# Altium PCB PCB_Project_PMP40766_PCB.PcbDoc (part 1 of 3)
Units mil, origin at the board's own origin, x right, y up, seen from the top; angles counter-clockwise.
Board outline 7480.31 x 3937.01 mil, 2 copper layers (Top Layer, Bottom Layer), stack 64.8 mil thick; 214 components, 118 nets, 518 pads, 70 vias.
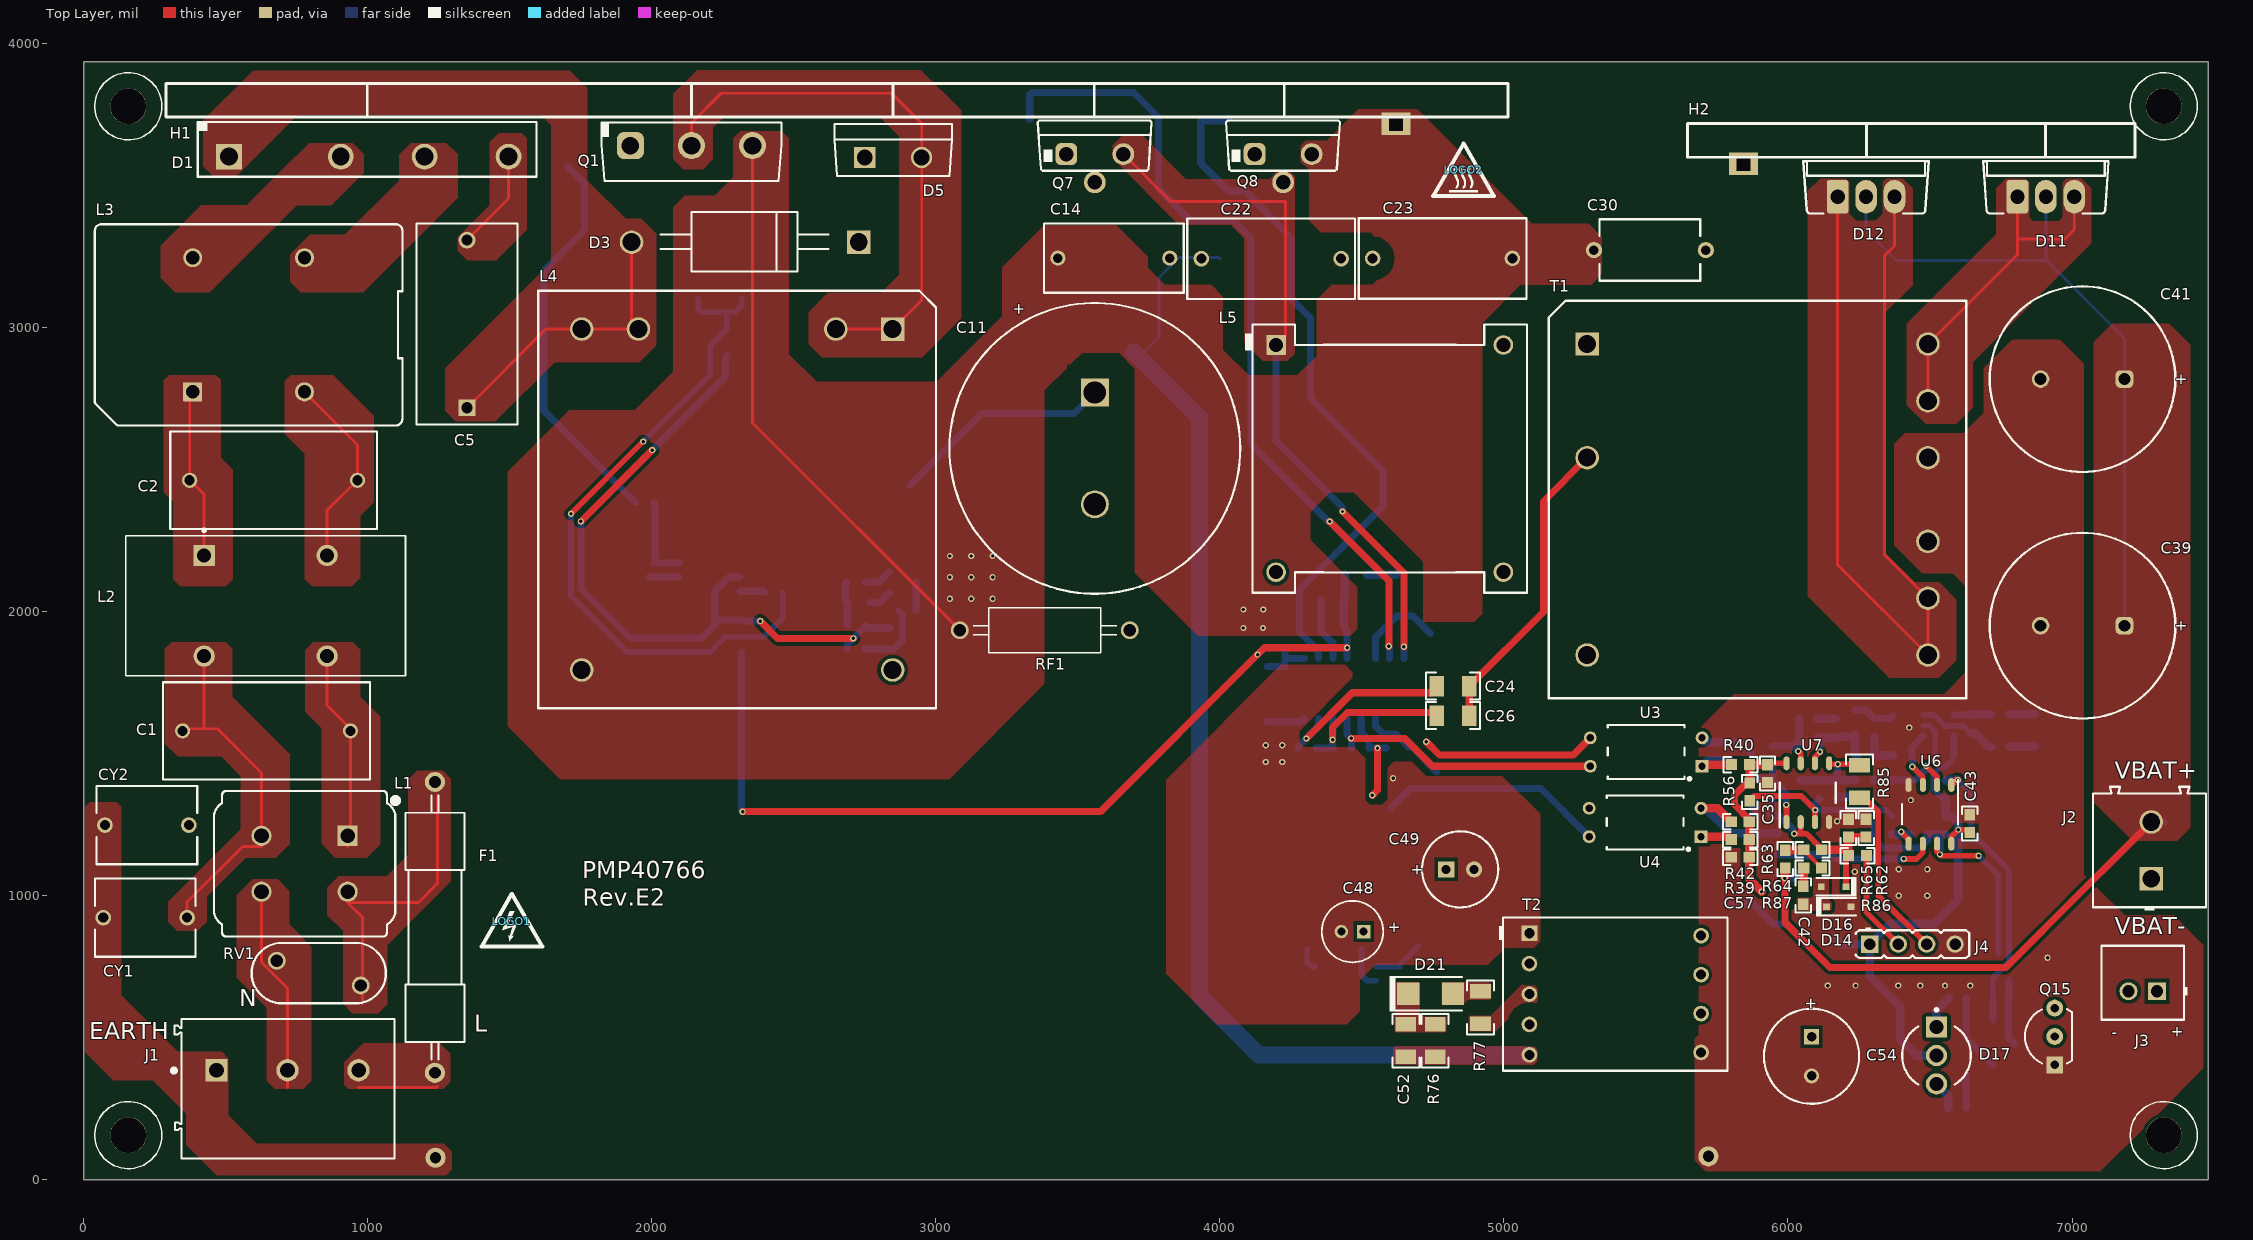
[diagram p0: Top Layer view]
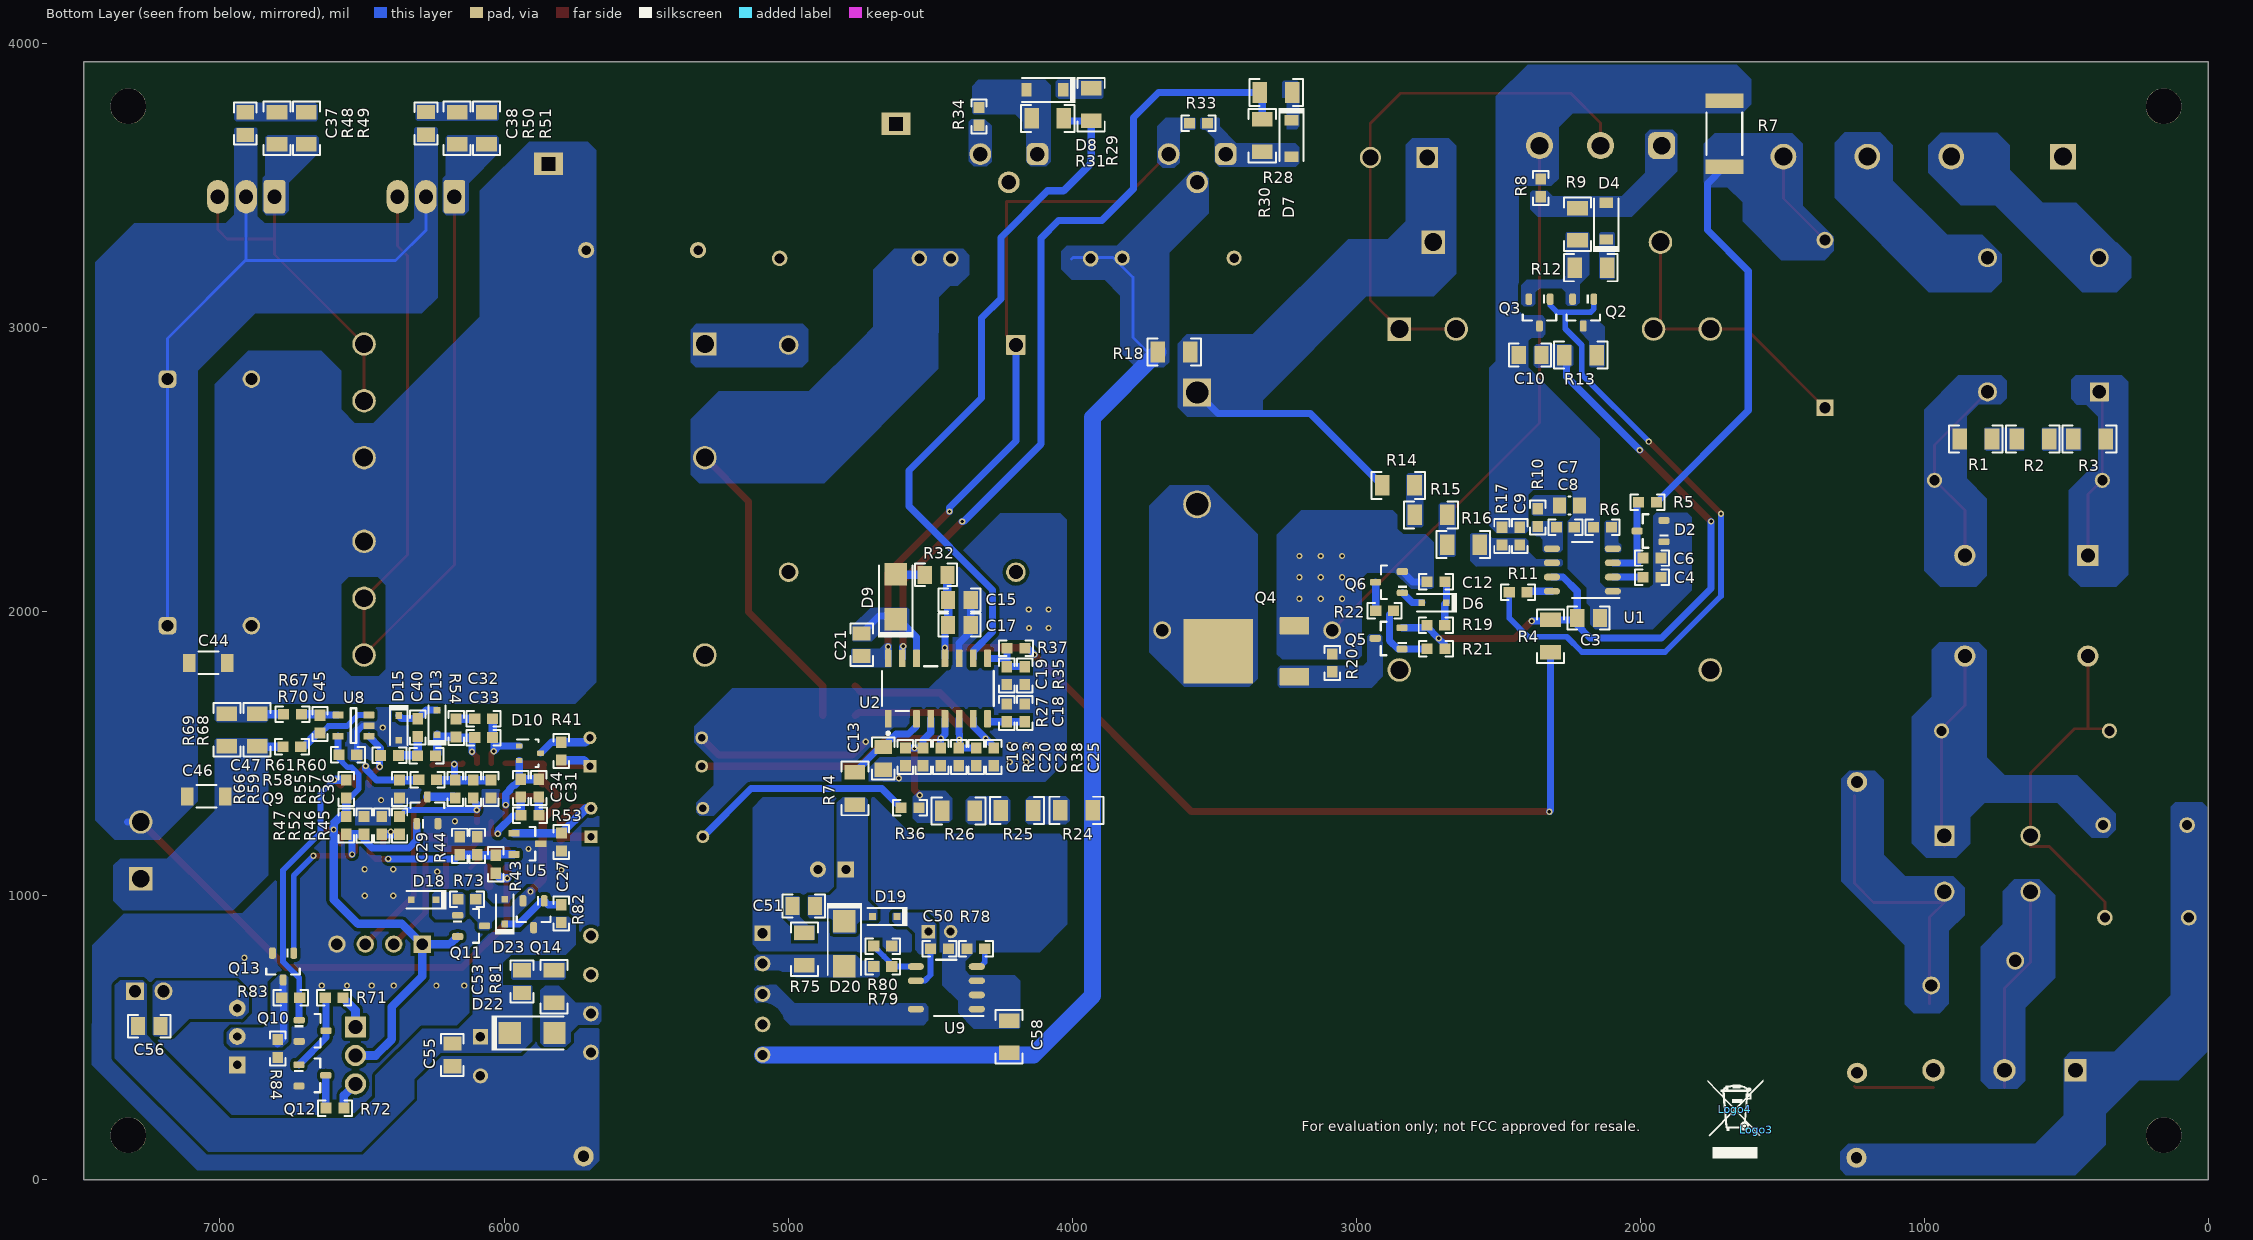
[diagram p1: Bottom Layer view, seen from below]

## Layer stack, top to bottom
Top Solder: solder mask 0.4, Solder Resist, Dk 3.5
Top Layer: signal copper 2.8
Dielectric1: core 59.2, FR-4, Dk 4.8
Bottom Layer: signal copper 2.8
Bottom Solder: solder mask 0.4, Solder Resist, Dk 3.5

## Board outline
0,0 7480.31,0 7480.31,3937.01 0,3937.01

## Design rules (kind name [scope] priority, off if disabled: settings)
AcuteAngle [All] p1: minimum=4.50000000000000E+0001 checktracksonly=FALSE
AssemblyTestPointUsage [All] p1: valid=2
Clearance Clearance_3 [InNet('EARTH') vs Not InNet('EARTH') And Not InNet('12VS')] p1: gap=129.92 ignorepadtopadclearanceinfootprint=FALSE
Clearance Clearance_1 [InNetClass('HV') vs InNetClass('MV')] p2: gap=25 ignorepadtopadclearanceinfootprint=FALSE except(0: Arc-Hole Track-Hole SMDPad-Hole THPad-Hole Via-Hole Fill-Hole Poly-Hole Region-Hole Text-Hole)
Clearance Clearance_2 [InNetClass('HV') vs Not InNetClass('HV')] p3: gap=50 ignorepadtopadclearanceinfootprint=FALSE except(0: Arc-Hole Track-Hole SMDPad-Hole THPad-Hole Via-Hole Fill-Hole Poly-Hole Region-Hole Text-Hole)
Clearance Clearance_Keepouts [((IsTrack Or IsArc) And Not InPoly) And IsFree and IsKeepOut vs ((IsTrack Or IsArc) And Not InPoly) And IsFree and IsKeepOut] p4: gap=0 ignorepadtopadclearanceinfootprint=FALSE
Clearance Clearance_BoardEdge_MountingHoles [OnCopper and InComponentClass('Mounting Holes') vs IsKeepOut] p5: gap=40 ignorepadtopadclearanceinfootprint=FALSE except(0: Arc-Hole Track-Hole SMDPad-Hole THPad-Hole Via-Hole Fill-Hole Poly-Hole Region-Hole Text-Hole)
Clearance Clearance_BoardEdge_Poly [OnCopper and InPoly vs IsKeepOut] p6: gap=25 ignorepadtopadclearanceinfootprint=FALSE except(0: Arc-Hole Track-Hole SMDPad-Hole THPad-Hole Via-Hole Fill-Hole Poly-Hole Region-Hole Text-Hole)
Clearance Clearance_BoardEdge [OnCopper and Not InComponentClass('Logo') and not InComponentClass('FiducialMark') and not InRegion(1000,500,4000,800) and Not IsKeepout vs IsKeepOut] p7: gap=75 ignorepadtopadclearanceinfootprint=FALSE except(0: Arc-Hole Track-Hole SMDPad-Hole THPad-Hole Via-Hole Fill-Hole Poly-Hole Region-Hole Text-Hole)
Clearance Clearance_Poly [InPolygon] p8: gap=12 ignorepadtopadclearanceinfootprint=FALSE
Clearance [All] p9: gap=7.87 ignorepadtopadclearanceinfootprint=FALSE except(0: Arc-Hole Track-Hole SMDPad-Hole THPad-Hole Via-Hole Fill-Hole Poly-Hole Region-Hole Text-Hole)
ComponentClearance ComponentClearance_MountingHoles_FiducialMarks [InComponentClass('Mounting Holes') vs InComponentClass('FiducialMark')] p1: gap=20 collisioncheckmode=3 verticalgap=10 showdistances=FALSE
ComponentClearance ComponentClearance_Shunt [InComponentClass('Header') vs InComponentClass('Shunt')] p2: gap=0 collisioncheckmode=3 verticalgap=0 showdistances=FALSE
ComponentClearance ComponentClearance_Logo [InComponentClass('Logo')] p3: gap=5 collisioncheckmode=3 verticalgap=10 showdistances=FALSE
ComponentClearance ComponentClearance_ScrewToNut [(HasFootprint('NY PMS 440 0025 PH')) vs (HasFootprint('Keystone_1902C'))] p4: gap=20 collisioncheckmode=3 verticalgap=100000 showdistances=FALSE
ComponentClearance ComponentClearance_MountingHoles [InComponentClass('Mounting Holes')] p5: gap=20 collisioncheckmode=3 verticalgap=10 showdistances=FALSE
ComponentClearance ComponentClearance_SmallPassives [HasFootprint('0201*') or HasFootprint('0402*') or HasFootprint('0508') or HasFootprint('0603*') or HasFootprint('0612') or HasFootprint('0805*') or HasFootprint('0815*') or HasFootprint('0830*') or HasFootprint('1206*') or HasFootprint('1210*') or HasFootprint('1808*') or HasFootprint('1812*') or HasFootprint('1825*') or HasFootprint('2010*') or HasFootprint('2220*') or HasFootprint('2225*') or HasFootprint('2512*') or HasFootprint('2728*') or HasFootprint('3518*') vs HasFootprint('0201*') or HasFootprint('0402*') or HasFootprint('0508') or HasFootprint('0603*') or HasFootprint('0612') or HasFootprint('0805*') or HasFootprint('0815*') or HasFootprint('0830*') or HasFootprint('1206*') or HasFootprint('1210*') or HasFootprint('1808*') or HasFootprint('1812*') or HasFootprint('1825*') or HasFootprint('2010*') or HasFootprint('2220*') or HasFootprint('2225*') or HasFootprint('2512*') or HasFootprint('2728*') or HasFootprint('3518*')] p6: gap=20 collisioncheckmode=3 verticalgap=20 showdistances=FALSE
ComponentClearance ComponentClearance_THtoSMT [IsThruComponent vs IsSMTComponent] p7: gap=10 collisioncheckmode=3 verticalgap=10 showdistances=FALSE
ComponentClearance ComponentClearance_THtoTH [IsThruComponent vs IsThruComponent] p8: gap=10 collisioncheckmode=3 verticalgap=10 showdistances=FALSE
ComponentClearance [All] p9: gap=10 collisioncheckmode=3 verticalgap=10 showdistances=FALSE
DiffPairsRouting [All] p1: maxlimit=100 minlimit=10 mostfreqgap=10 toplayer_minwidth=15 toplayer_maxwidth=15 toplayer_prefwidth=15 bottomlayer_minwidth=15 bottomlayer_maxwidth=15 bottomlayer_prefwidth=15 maxuncoupledlength=1000
FabricationTestPointUsage TestPointUsage [All] p1: valid=2 allowmultiple=FALSE
FabricationTestpoint Testpoint [All] p1: side=3 testpointundercomponent=TRUE minsize=40 maxsize=100 preferedsize=60 minholesize=0 maxholesize=40 preferedholesize=32 testpointgrid=1 allowsidetop=TRUE allowsidebottom=TRUE usegrid=TRUE gridtolerance=0.01
FanoutControl Fanout_LCC [IsLCC] p1: bgadir=Out bgaviamode=Centered fanoutstyle=Auto fanoutdirection=Alternating viagrid=1 // Fanout_LCC (Default Rule)
FanoutControl Fanout_BGA [IsBGA] p2: bgadir=Out bgaviamode=Centered fanoutstyle=Auto fanoutdirection=Alternating viagrid=1 // Fanout_BGA (Default Rule)
FanoutControl Fanout_Default [All] p4: bgadir=Out bgaviamode=Centered fanoutstyle=Auto fanoutdirection=Alternating viagrid=1 // Fanout_Default (Default Rule)
FanoutControl Fanout_Small [(CompPinCount < 5)] p5: bgadir=Out bgaviamode=Centered fanoutstyle=Auto fanoutdirection=OutThenIn viagrid=1 // Fanout_Small (Default Rule)
Height [All] p1: minheight=0 maxheight=3000 prefheight=500
HoleSize [All] p1: absolutevalues=TRUE maxlimit=251 minlimit=7 maxpercent=80.000 minpercent=20.000
MinimumAnnularRing MinimumAnnularRing_ThermalPadVias [IsVia and InAnyComponent] p1: minimumring=5.91
MinimumAnnularRing [All] p2: minimumring=4.9
MinimumSolderMaskSliver MinimumSolderMaskSliver_Logo [InComponentClass('Logo') vs InComponentClass('Logo')] p1: minsoldermaskwidth=0.7
MinimumSolderMaskSliver [All] p2: minsoldermaskwidth=2
PlaneConnect [All] p1: planeconnectstyle=Direct reliefexpansion=10 reliefentries=4 reliefconductorwidth=10 reliefairgap=10
PolygonConnect [All] p1: connectstyle=Direct reliefconductorwidth=10 reliefentries=4 polygonreliefangle="90 Angle" airgapwidth=10
RoutingVias ThermalPadVias [IsVia and InAnyComponent] p1: holewidth=7.87 width=19.68 viastyle="Through Hole" minholewidth=7.87 minwidth=19.68 maxholewidth=12.99 maxwidth=23.62
RoutingVias [All] p2: holewidth=16 width=34 viastyle="Through Hole" minholewidth=7.87 minwidth=20 maxholewidth=40 maxwidth=65
SilkToBoardRegionClearance [Not ((IsComment or IsDesignator) And (Hide <> 'False')) and not InRegion(1000,500,4000,800)] p1:
SilkToSilkClearance SilkToSilkClearance_Pb-FreeLogo [(HasFootprint('Pb-Free_Overlay_Medium') OR HasFootprint('Pb-Free_Overlay_Small')) vs (HasFootprint('Pb-Free_Overlay_Medium') OR HasFootprint('Pb-Free_Overlay_Small'))] p1: silktosilkclearance=0
SilkToSilkClearance [All] p2: silktosilkclearance=1
SilkToSolderMaskClearance "Silk to Solder Mask Opening" [All] p1: minsilkscreentomaskgap=1 clearancetoexposedcopper=FALSE
SolderMaskExpansion [All] p1: expansion=1.97
Width [All] p1: maxlimit=100 minlimit=6 preferedwidth=10 checkconnectedcopper=TRUE
14 further rules are at their usual default settings.

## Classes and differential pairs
net class HV: HB HO HS "N Wire" NetC1_1 NetC1_2 NetC2_1 NetC2_2 NetC5_1 NetC11_1 NetC22_2 NetC52_2 NetD1_2 NetD1_3 NetD5_2 NetD7_1 NetD7_2 NetD21_2 NetF1_1 NetR77_1 VBUS
component class PCB_Project_PMP40766_BlankSheet: C13 C14 C15 C16 C17 C18 C19 C20 C21 C22 C23 C24 C25 C26 C27 C28 C29 C30 C31 C32 C33 C34 C35 C36 C37 C38 C39 C40 C41 C42 C43 C44 C45 C46 C47 D7 D8 D9 D10 D11 D12 D13 D14 D15 D16 D17 D18 H1 H2 J2 L5 Q7 Q8 Q9 Q10 Q11 Q12 R23 R24 R25 R26 R27 R28 R29 R30 R31 R32 R33 R34 R35 R36 R37 R38 R39 R40 R41 R42 R43 R44 R45 R46 R47 R48 R49 R50 R51 R52 R53 R54 R55 R56 R57 R58 R59 R60 R61 R62 R63 R64 R65 R66 R67 R68 R69 R70 R71 R72 R73 R87 T1 U2 U3 U4 U5 U6 U7 U8
component class PCB_Project_PMP40766_CoverSheet: C1 C2 C3 C4 C5 C6 C7 C8 C9 C10 C11 C12 CY1 CY2 D1 D2 D3 D4 D5 D6 F1 J1 L1 L2 L3 L4 Q1 Q2 Q3 Q4 Q5 Q6 R1 R2 R3 R4 R5 R6 R7 R8 R9 R10 R11 R12 R13 R14 R15 R16 R17 R18 R19 R20 R21 R22 RF1 RV1 U1
component class PCB_Project_PMP40766_EVM_Hardware: C48 C49 C50 C51 C52 C53 C54 C55 C56 C57 C58 D19 D20 D21 D22 D23 J3 J4 LOGO1 LOGO2 Logo3 Logo4 Q13 Q14 Q15 R74 R75 R76 R77 R78 R79 R80 R81 R82 R83 R84 R85 R86 T2 U9
component class Header: J4

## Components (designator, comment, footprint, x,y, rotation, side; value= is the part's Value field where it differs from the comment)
C1 "R46KI347050P0K" Kemet_1800x850x1450 644,1581 r180 top value=0.47uF
C2 "R46KI347050P0K" Kemet_1800x850x1450 669,2463 r0 top value=0.47uF
C3 "GRM21BR71E475KA73L" 0805_HV 2182,1978.26 r180 bottom value=4.7uF
C4 "GRM1885C1H222JA01D" 0603 1959,2121.26 r180 bottom value=2200pF
C5 "ECW-FD2W125K" B32922_17.5mm 1350,3013.26 r90 top value=1.2uF
C6 "GRM1885C1H102FA01J" 0603 1959,2189.26 r180 bottom value=1000pF
C7 "08053C225KAT2A" 0805_150 2249,2374.26 r180 bottom value=2.2uF
C8 "C0603C105K3RACTU" 0603 2264,2297.26 r180 bottom value=1uF
C9 "GRM1885C1H271JA01D" 0603 2425,2266.26 r90 bottom value=270pF
C10 "C2012X7R1H225K125AC" 0805_HV 2388,2904.26 r0 bottom value=2.2uF
C11 "450HXG220MEFCSN25X40" HXG_2500x4000 3560,2575.26 r270 top value=220uF
C12 "GRM188R71E474KA12D" 0603 2719,2105.26 r0 bottom value=0.47uF
C13 "C2012X7R1H225K125AC" 0805_HV 4665,1484.26 r270 bottom value=2.2uF
C14 "ECW-F6223HL" ECWF_L_1250x620x1050 3627,3245 r180 top value=0.022uF
C15 "GRM21BR71E475KA73L" 0805_HV 4397,2041.26 r180 bottom value=4.7uF
C16 "GRM188R71E104KA01D" 0603 4525,1489.26 r270 bottom value=0.1uF
C17 "GRM21BR71E475KA73L" 0805_HV 4397,1953.26 r180 bottom value=4.7uF
C18 "06035A3R9CAT2A" 0603 4166.93,1644.26 r90 bottom value=3.9pF
C19 "C0603C474K4RACTU" 0603 4230,1775.26 r270 bottom value=0.47uF
C20 "GRM1885C1H101JA01D" 0603 4463,1489.26 r270 bottom value=100pF
C21 "GRM21BR71E225KA73L" 0805_HV 4741,1884 r90 bottom value=2.2uF
C22 "ECW-H8223HA" WCAP-FTX2_1500x700x1250 4181,3243 r0 top value=0.022uF
C23 "ECW-H8223HA" WCAP-FTX2_1500x700x1250 4784,3244 r0 top value=0.022uF
C24 "VJ1206A470JXGAT5Z" 1206 4821,1738.26 r180 top value=47pF
C25 "GRM188R71H822KA01D" 0603 4276,1489.26 r270 bottom value=8200pF
C26 "VJ1206A470JXGAT5Z" 1206 4821,1634.26 r180 top value=47pF
C27 "GRM188R71E224KA88D" 0603 5798,1189.26 r270 bottom value=0.22uF
C28 "GRM1885C1H101JA01D" 0603 4400,1489.26 r270 bottom value=100pF
C29 "GRM188R71E104KA01D" 0603 6156,1176.26 r90 bottom value=0.1uF
C30 "C921U222MVVDBA7317" C900_9x13 5514,3273.26 r180 top value=2200pF
C31 "C0603X103K5RACTU" 0603 5878,1379.26 r270 bottom value=0.01uF
C32 "GRM188R71E104KA01D" 0603 6072,1623.26 r0 bottom value=0.1uF
C33 "GRM188R71E102KA01D" 0603 6072,1557.26 r180 bottom value=1000pF
C34 "C0603X471K5RACTU" 0603 5941,1379.26 r90 bottom value=470pF
C35 "GRM188R71E104KA01D" 0603 5928,1430.26 r270 top value=0.1uF
C36 "GRM188R71E104KA01D" 0603 6046,1376.26 r90 bottom value=0.1uF
C37 "CL21C101JECNNWC" 0805_HV 6911,3718.37 r90 bottom value=100pF
C38 "CL21C101JECNNWC" 0805_HV 6275,3719.26 r90 bottom value=100pF
C39 "EEUFS1K681" UES_1600x2500 7037,1951.26 r180 top value=680uF
C40 "C1608X7R1E224K080AC" 0603 6304,1592.26 r90 bottom value=0.22uF
C41 "EEUFS1K681" UES_1600x2500 7037,2819.26 r180 top value=680uF
C42 "C0603X103K1RACTU" 0603 6054,1002 r270 top value=0.01uF
C43 "GRM188R71E104KA01D" 0603 6640,1254.26 r90 top value=0.1uF
C44 "GRM31CR72A105KA01L" 1206_180 7041,1820.26 r180 bottom value=1uF
C45 "GRM188R71E104KA01D" 0603 6648,1604.26 r270 bottom value=0.1uF
C46 "GRM31CR72A105KA01L" 1206_180 7048,1350.26 r180 bottom value=1uF
C47 "GRM188R71E104KA01D" 0603 6550,1496.26 r180 bottom value=0.1uF
C48 "25ML22MEFC5X5" ML_500x500 4467,874.26 r180 top value=22uF
C49 "EEU-FM1E101" FM_630x1120 4846,1093.26 r0 top value=100uF
C50 "C1608X7R1E105K080AE" 0603 4467,814.26 r180 bottom value=1uF
C51 "08051A471JAT2A" 0805_HV 4945,964.26 r180 bottom value=470pF
C52 "GRM31BR72J222KW01L" 1206 4655,490.26 r90 top value=2200pF
C53 "08051A471JAT2A" 0805_HV 5937,698.26 r90 bottom value=470pF
C54 "EKZE250ELL221MHB5D" Chemi-Con_800x1150 6083,435.26 r270 top value=220uF
C55 "GRM216R61E105KA12D" 0805_HV 6182,440.26 r270 bottom value=1uF
C56 "GRM216R61E105KA12D" 0805_HV 7249,541.26 r180 bottom value=1uF
C57 "GRM188R71E104KA01D" 0603 5832,1136.26 r180 top value=0.1uF
C58 "GRM31BR72J222KW01L" 1206 4222,504 r90 bottom value=2200pF
CY1 "DE6E3KJ222MN3A" E_900x700x900 217,923.26 r0 top value=2200pF
CY2 "DE6E3KJ222MN3A" E_900x700x900 223,1249.26 r180 top value=2200pF
D1 "GBJ2506-BP" GBJ 1004,3602.26 r0 top value=600V
D2 "BAV23CLT1G" SOT-23 1964,2284.26 r0 bottom value=250V
D3 "1N5406" DO-201AD 2329,3301.26 r180 top value=600V
D4 "1N4148W-7-F" SOD-123 2120,3375.26 r90 bottom value=100V
D5 "C3D04060A" TO-220-F2 2850,3599.26 r0 top value=600V
D6 "MM3Z5V1ST1G" SOD-323 2726,2032.26 r0 bottom value=5.1V
D7 "1N4148W-7-F" SOD-123 3228,3666.26 r270 bottom value=100V
D8 "1N4148W-7-F" SOD-123 4096,3837.26 r0 bottom value=100V
D9 "ES1JTR" SMA 4621,2053 r90 bottom value=600V
D10 "BAT54AWT-TP" SOT-323 5909,1502.26 r180 bottom value=30V
D11 "TST20L200CW C0G" TO-220AB 6908,3461.26 r0 top value=200V
D12 "TST20L200CW C0G" TO-220AB 6275,3461.26 r0 top value=200V
D13 "BAT43WS-7-F" SOD-323 6236,1610.26 r90 bottom value=30V
D14 "BAT43WS-7-F" SOD-323 6179,962 r0 top value=30V
D15 "BAT43WS-7-F" SOD-323 6371,1591.26 r270 bottom value=30V
D16 "BAT43WS-7-F" SOD-323 6161,1032 r180 top value=30V
D17 "MT6224-AHRG-A" FP-MT6224-AHRG-A_RADIAL-MFG 6523,438 r270 top
D18 "MM3Z5V6ST1G" SOD-323 6283,986.26 r0 bottom value=5.6V
D19 "1N4148WX-TP" SOD-323 4660,927.26 r0 bottom value=75V
D20 "ES1D-13-F" SMA 4802,831.26 r270 bottom value=200V
D21 "US1M-13-F" SMA 4742,655.26 r0 top value=1000V
D22 "ES1D-13-F" SMA 5901,517.26 r180 bottom value=200V
D23 "MM3Z11VST1G" SOD-323 5998,944.26 r90 bottom value=11V
F1 "0216010.MXEP" FUSE_0216 1237,889 r270 top
H1 "40mm*120mm" Heatsink1 290,3741.26 r0 top
H2 "" Heatsink2 5647,3600.26 r0 top
J1 "1714968" Phoenix_1714968 718,386 r0 top
J2 "691216510002S" Wurth_691216510002 7279,1160.26 r90 top
J3 "705430001" Molex_0705430001 7249,664.26 r180 top
J4 "22284043" Molex_0022284043 6438.44,830 r0 top
L1 "744842932" WE-CMB_NiZn_S 778,1113 r270 top value=32uH
L2 "YXBCM020013007C" FP-YXBCM020013007C_PTH_CHOKE_12MM5_25MM0-MFG 641,2021.26 r90 top
L3 "7448040707" WE-CMBNC_L 581,3010.26 r90 top value=7mH
L4 "" PQ3230_1 2301,2395.26 r270 top value=340uH
L5 "" PQ2020 4598,2539.26 r0 top value=58uH
LOGO1 "DANGER HIGH VOLTAGE" IEC_HighVoltage_Small 1508,910 r0 top
LOGO2 "CAUTION HOT SURFACE" IEC_HotSurface_Small 4858,3556.26 r0 top
Logo3 "FCC disclaimer" FCC_disclaimer 1592,177 r180 bottom
Logo4 "WEEE logo" WEEE_Minimum 1667,248 r180 bottom
Q1 "IPW60R080P7XKSA1" TO-247 2140,3641.26 r0 top value=600V
Q2 "MMBT2222ALT1G" SOT-23 2201,3053.26 r270 bottom value="40 V"
Q3 "MMBT2907ALT1G" SOT-23 2355,3053.26 r270 bottom value="60 V"
Q4 "IPD60R180P7SAUMA1" DPAK 3352,1861.26 r0 bottom value=600V
Q5 "MMBT3906LT1G" SOT-23 2886,1906.26 r0 bottom value="40 V"
Q6 "MMBT3904LT1G" SOT-23 2885,2104.26 r0 bottom value="40 V"
Q7 "IPA60R170CFD7XKSA1" TO-220FP 3560,3611.26 r0 top value=600V
Q8 "IPA60R170CFD7XKSA1" TO-220FP 4223,3611.26 r0 top value=600V
Q9 "2N7002-7-F" SOT-23 6270,1301.26 r90 bottom value=60V
Q10 "2N7002-7-F" SOT-23 6674,525 r180 bottom value=60V
Q11 "MMBT3904LT1G" SOT-23 6116,894.26 r180 bottom value="40 V"
Q12 "2N7002-7-F" SOT-23 6675,368 r180 bottom value=60V
Q13 "2N7002-7-F" SOT-23 6778,751 r270 bottom value=60V
Q14 "MMBT3904LT1G" SOT-23 5896,935.26 r270 bottom value="40 V"
Q15 "2N4401-AP" TO-92AP 6939,505 r90 top value="40 V"
R1 "RC1206FR-07330KL" 1206 819,2608.26 r0 bottom value=330k
R2 "RC1206FR-07330KL" 1206 618,2608.26 r0 bottom value=330k
R3 "RC1206FR-07330KL" 1206 419,2608.26 r0 bottom value=330k
R4 "RC1206JR-070RL" 1206 2316,1914.26 r90 bottom value=0
R5 "RC0603FR-07220RL" 0603 1975,2385.26 r180 bottom value=220
R6 "RC0603FR-0721K5L" 0603 2133,2298.26 r180 bottom value=21.5k
R7 "CSRN2512FK20L0" 2512 1704,3683.26 r90 bottom value=0.02
R8 "RC0603FR-0710KL" 0603 2350,3492.26 r270 bottom value=10.0k
R9 "RC1206FR-073R3L" 1206 2221,3364.26 r90 bottom value=3.30
R10 "RC0603FR-0711K5L" 0603 2361,2331.26 r270 bottom value=11.5k
R11 "RC0603FR-0710RL" 0603 2430,2068.26 r0 bottom value=10.0
R12 "RC1206FR-073R3L" 1206 2174,3211.26 r180 bottom value=3.30
R13 "RC1206FR-073R3L" 1206 2210,2903.26 r180 bottom value=3.30
R14 "RC1206FR-071ML" 1206 2852,2445.26 r0 bottom value=1.00Meg
R15 "RC1206FR-071ML" 1206 2737,2341.26 r0 bottom value=1.00Meg
R16 "RC1206FR-071ML" 1206 2623,2236.26 r0 bottom value=1.00Meg
R17 "RC0603FR-0739KL" 0603 2487,2266.26 r270 bottom value=39.0k
R18 "RC1206JR-070RL" 1206 3641,2914.26 r0 bottom value=0
R19 "RC0603FR-07100KL" 0603 2720,1952.26 r0 bottom value=100k
R20 "RC0603FR-0710KL" 0603 3084,1820.26 r270 bottom value=10.0k
R21 "RC0603FR-07100KL" 0603 2719,1869.26 r180 bottom value=100k
R22 "RC0603FR-07100KL" 0603 2900,2004.26 r180 bottom value=100k
R23 "RC0603FR-07121KL" 0603 4587,1489.26 r90 bottom value=121k
R24 "CRCW12064M99FKEA" 1206 3985,1301.26 r180 bottom value=4.99Meg
R25 "CRCW12064M99FKEA" 1206 4194,1300.26 r180 bottom value=4.99Meg
R26 "CRCW12064M99FKEA" 1206 4400,1299.26 r180 bottom value=4.99Meg
R27 "RC0603FR-074K53L" 0603 4230,1644.26 r270 bottom value=4.53k
R28 "RC1206FR-071RL" 1206 3282,3828.26 r180 bottom value=1.00
R29 "RC1206FR-071RL" 1206 3933,3785.26 r90 bottom value=1.00
R30 "RC1206FR-0710RL" 1206 3331,3676.26 r270 bottom value=10.0
R31 "RC1206FR-0710RL" 1206 4086,3737.26 r0 bottom value=10.0
R32 "RC0805FR-072R2L" 0805_HV 4479,2130 r0 bottom value=2.20
R33 "RC0603FR-0710KL" 0603 3555,3719.26 r180 bottom value=10.0k
R34 "RC0603FR-0710KL" 0603 4328,3744.26 r90 bottom value=10.0k
R35 "RC0603FR-0782KL" 0603 4167,1775.26 r90 bottom value=82.0k
R36 "RC0603FR-0751KL" 0603 4571,1310.26 r180 bottom value=51.0k
R37 "RC0603FR-07200KL" 0603 4198,1871.26 r0 bottom value=200k
R38 "RC0603FR-07180RL" 0603 4338,1489.26 r90 bottom value=180
R39 "RC0603FR-073KL" 0603 5832,1198.26 r0 top value=3.00k
R40 "RC0603FR-076K04L" 0603 5833,1462.26 r0 top value=6.04k
R41 "RC0603FR-073KL" 0603 5799,1509.26 r90 bottom value=3.00k
R42 "RC0603FR-0710KL" 0603 5832,1260.26 r0 top value=10.0k
R43 "RC0603FR-07301KL" 0603 6029,1111.26 r270 bottom value=301k
R44 "RC0603FR-0710KL" 0603 6094,1176.26 r270 bottom value=10.0k
R45 "RC0603FR-075K1L" 0603 6368,1248.26 r90 bottom value=5.10k
R46 "RC0603FR-077K5L" 0603 6431,1248.26 r270 bottom value=7.50k
R47 "RC0603FR-075K1L" 0603 6555,1248.26 r90 bottom value=5.10k
R48 "RC1206FR-0710RL" 1206 6799,3702.26 r90 bottom value=10.0
R49 "RC1206FR-0710RL" 1206 6696,3702.26 r90 bottom value=10.0
R50 "RC1206FR-0710RL" 1206 6165,3702.26 r90 bottom value=10.0
R51 "RC1206FR-0710RL" 1206 6062,3702.26 r90 bottom value=10.0
R52 "RC0603FR-0710KL" 0603 6493,1248.26 r270 bottom value=10.0k
R53 "RC0603FR-0768KL" 0603 5909,1284.26 r180 bottom value=68.0k
R54 "RC0603FR-072K4L" 0603 6169,1591.26 r270 bottom value=2.40k
R55 "RC0603FR-07187RL" 0603 6172,1376.26 r90 bottom value=187
R56 "RC0603FR-073KL" 0603 5866,1366.26 r270 top value=3.00k
R57 "RC0603FR-072K4L" 0603 6109,1376.26 r270 bottom value=2.40k
R58 "RC0603FR-075K1L" 0603 6269,1408.26 r180 bottom value=5.10k
R59 "RC0603FR-07499RL" 0603 6368,1376.26 r90 bottom value=499
R60 "RC0603FR-072KL" 0603 6273,1493.26 r0 bottom value=2.00k
R61 "RC0603FR-0720RL" 0603 6403,1494.26 r180 bottom value=20.0
R62 "CRCW060312K4FKEA" 0603 6275,1238.26 r270 top value=12.4k
R63 "RC0603FR-0720RL" 0603 5991,1129.26 r270 top value=20.0
R64 "RC0603FR-07100KL" 0603 6087,1162.26 r180 top value=100k
R65 "RC0603FR-075K11L" 0603 6213,1238.26 r270 top value=5.11k
R66 "RC0603FR-071KL" 0603 6556,1376.26 r90 bottom value=1.00k
R67 "RC0603FR-0710RL" 0603 6745,1639.26 r0 bottom value=10.0
R68 "CSR1206FK10L0" 1206 6869,1584.26 r270 bottom value=0.01
R69 "CSR1206FK10L0" 1206 6976,1584.26 r270 bottom value=0.01
R70 "RC0603FR-0710RL" 0603 6747,1524.26 r0 bottom value=10.0
R71 "RC0603FR-07510RL" 0603 6598,641 r180 bottom value=510
R72 "RC0603FR-07510RL" 0603 6595,253 r180 bottom value=510
R73 "RC0603FR-073K6L" 0603 6131,988.26 r0 bottom value=3.60k
R74 "RC1206JR-070RL" 1206 4765,1378.26 r270 bottom value=0
R75 "RC1206FR-0710RL" 1206 4943,812.26 r270 bottom value=10.0
R76 "RC1206FR-07200KL" 1206 4758,490.26 r270 top value=200k
R77 "RC1206FR-07200RL" 1206 4918,607.26 r90 top value=200
R78 "RC0603FR-071K8L" 0603 4339,813.26 r180 bottom value=1.80k
R79 "RC0603FR-0782KL" 0603 4667,751.26 r0 bottom value=82.0k
R80 "RC0603FR-0730KL" 0603 4667,823.26 r0 bottom value=30.0k
R81 "RC1206FR-0710RL" 1206 5824,680.26 r90 bottom value=10.0
R82 "RC0603FR-073KL" 0603 5799,937.26 r90 bottom value=3.00k
R83 "RC0603FR-071KL" 0603 6751,641 r180 bottom value=1.00k
R84 "RC0603FR-0710KL" 0603 6797,463 r90 bottom value=10.0k
R85 "RC1206FR-0710KL" 1206 6252,1402.5 r270 top value=10.0k
R86 "RC0603FR-0710KL" 0603 6245,1142 r180 top value=10.0k
R87 "RC0603FR-07150KL" 0603 6087,1098 r0 top value=150k
RF1 "EMC2-47RKI" EMC2 3384,1935.26 r180 top value=47
RV1 "S10K275E2" VAR_S10K275E2 828,728 r180 top value=275V
T1 "" PQ3230_2 5893,2395.26 r0 top value=200uH
T2 "RLTI-1168" Renco_RLTI-1186 5392,654.26 r0 top value=1800uH
U1 "UCC28180DR" D0008A_N 2204,2147.26 r0 bottom
U2 "UCC256403DDBR" DDB0014A-MFG 4473,1729.77 r90 bottom
U3 "FOD817A" DIP-4 5501,1506.26 r180 top
U4 "FOD817A" DIP-4 5497,1258.26 r180 top
U5 "TL431LIAIDBZR" DBZ0003A_N 5918,1183.26 r180 bottom
U6 "LMV393IDR" D0008A_L 6500,1287 r270 top
U7 "TL103WAIDR" D0008A_L 6070,1363.26 r90 top
U8 "INA180A2IDBVR" DBV0005A_N 6530,1599.26 r0 bottom
U9 "UCC28910DR" D0007A_N 4443,676.26 r0 bottom

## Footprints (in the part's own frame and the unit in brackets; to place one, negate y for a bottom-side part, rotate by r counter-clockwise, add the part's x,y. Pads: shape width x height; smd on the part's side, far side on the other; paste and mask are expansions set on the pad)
0603 [mm] "0603 from SM-752 data"
  rect 1x0.95 smd: 1(-0.8,0) 2(0.8,0)
  silkscreen extent -1.52,-0.69 1.52,0.69, body extent -0.87,-0.47 0.87,0.47, height 1
0805_150 [mm] "0805 / 1.5 mm height"
  rect 1.15x1.45 smd: 1(-0.9,0) 2(0.9,0)
  silkscreen extent -0.1,-0.8 0.1,0.8, body extent -1.1,-0.72 1.1,0.72, height 1.5
0805_HV [mil] "0805 with 30mil clearance between pads"
  rect 50x63 smd: 1(-40,0) 2(40,0)
  silkscreen extent -74,-40 74,40, body extent -43,-29 43,29, height 57
1206 [mm] "1206 from SM-752 data"
  rect 1.3x1.85 smd: 1(-1.45,0) 2(1.45,0)
  silkscreen extent -2.4,-1.21 2.4,1.21, body extent -1.7,-0.9 1.7,0.9, height 1.35
1206_180 [mm] "1206_180"
  rect 1.1x1.6 smd: 1(-1.7,0) 2(1.7,0)
  silkscreen extent -0.9,-1 0.9,1, body extent -1.75,-0.95 1.75,0.95, height 1.8
2512 [mm] "Chip Resistor, Body 6.3x3.2mm, IPC Medium Density"
  rect 1.3x3.4 smd: 1(-2.95,0) 2(2.95,0)
  silkscreen extent -1.9,-1.6 1.9,1.6, body extent -3.22,-1.67 3.22,1.67, height 0.71
B32922_17.5mm [mm] "Epcos film capacitors, 15mm spacing"
  rect 1.5x1.5 hole 1: 1(-7.5,0)
  round 1.5 hole 1: 2(7.5,0)
  silkscreen extent -9,-4.5 9,4.5, body extent -9,-4.5 9,4.5, height 17.5
C900_9x13 [mm] "Kemet"
  round 1.45 hole 0.85: 1(-5,0) 2(5,0)
  silkscreen extent -4.5,-2.75 4.5,2.75, body extent -4.49,-2.75 4.49,2.75, height 12.96
Chemi-Con_800x1150 [mm] "TH, 2-Leads, Dia 8mm"
  rect 1.35x1.35 hole 0.85: 1(-1.75,0)
  round 1.35 hole 0.85: 2(1.75,0)
  silkscreen extent -4.25,-4.25 4.25,4.25, body extent -4.22,-4.24 4.24,4.24, height 13.01
D0007A_N [mm] "SOIC, 7-Leads, Body 4.9x3.9mm, Pitch 1.27mm, IPC Medium Density"
  oval 1.45x0.6 smd: 1(-2.725,1.905) 2(-2.725,0.635) 3(-2.725,-0.635) 4(-2.725,-1.905) 5(2.725,-1.905) 6(2.725,-0.635) 8(2.725,1.905)
  silkscreen extent -3.32,-2.5 1.1,2.52, body extent -3.01,-2.45 3.01,2.45, height 1.75
D0008A_L [mm] "SOIC, 8-Leads, Body 4.9x3.9mm, Pitch 1.27mm, IPC High Density"
  oval 1.25x0.55 smd: 1(-2.625,1.905) 2(-2.625,0.635) 3(-2.625,-0.635) 4(-2.625,-1.905) 5(2.625,-1.905) 6(2.625,-0.635) 7(2.625,0.635) 8(2.625,1.905)
  silkscreen extent -3.1,-2.5 0.9,2.5, body extent -3,-2.45 3,2.45, height 1.63
D0008A_N [mm] "SOIC, 8-Leads, Body 4.9x3.9mm, Pitch 1.27mm, IPC Medium Density"
  oval 1.45x0.6 smd: 1(-2.725,1.905) 2(-2.725,0.635) 3(-2.725,-0.635) 4(-2.725,-1.905) 5(2.725,-1.905) 6(2.725,-0.635) 7(2.725,0.635) 8(2.725,1.905)
  silkscreen extent -3.3,-2.5 0.9,2.5, body extent -3,-2.45 3,2.45, height 1.63
DBV0005A_N [mm] "SOT23, 5-Leads, Body 2.9x1.6mm, Pitch 0.95mm, Lead Span 2.8mm, IPC Medium Density"
  rrect17% 1x0.6 smd: 1(-1.375,0.95) 2(-1.375,0) 3(-1.375,-0.95) 4(1.375,-0.95) 5(1.375,0.95)
  silkscreen extent -0.25,-1.55 0.25,1.55, body extent -1.42,-1.46 1.42,1.46, height 1.09
DBZ0003A_N [mm] "SOT23, 3-Leads, Body 2.9x1.3mm, Pitch 0.95mm, Lead Span 2.4mm, IPC Medium Density"
  rrect17% 1x0.6 smd: 1(-1.2,0.95) 2(-1.2,-0.95) 3(1.2,0)
  silkscreen extent 0.2,-1.5 0.7,1.5, body extent -1.26,-1.46 1.26,1.46, height 0.98
DDB0014A-MFG [mm]
  rrect17% 1.55x0.6 smd paste+0 mask+0: 1(-2.7,4.445) 3(-2.7,1.905) 4(-2.7,0.635) 5(-2.7,-0.635) 6(-2.7,-1.905) 7(-2.7,-3.175) 8(-2.7,-4.445) 9(2.7,-4.445) 10(2.7,-3.175) 11(2.7,-1.905) 12(2.7,-0.635) 14(2.7,1.905) 15(2.7,3.175) 16(2.7,4.445)
  silkscreen extent -4.12,-5 2,5, body extent -3.01,-4.95 3.01,4.95, height 1.75
DIP-4 [mm] "DIP, 4-Leads, Body 6.86x4.83mm, Pitch 2.54mm"
  rect 1.15x1.15 hole 0.65: 1(-5,1.27)
  round 1.15 hole 0.65: 2(-5,-1.27) 3(5,-1.27) 4(5,1.27)
  silkscreen extent -4,-2.41 3.43,2.52, body extent -4.44,-2.41 4.4,2.41, height 5.59
DO-201AD [mm] "Vishay dimensions"
  rect 2.1x2.1 hole 1.6: 1(-10.16,0)
  round 2.1 hole 1.6: 2(10.16,0)
  silkscreen extent -7.47,-2.7 7.57,2.61, body extent -10.82,-2.74 10.82,2.61, height 5.33
DPAK [mm] "D-PAK, 3-Pads, Body 6.22x6.73mm (max), TO-252AA using nominal STEP model"
  rrect6% 2.6x1.6 smd: 1(-3.4,2.28) 3(-3.4,-2.28)
  rrect2% 6.2x5.8 smd paste-3: 2(3.4,0)
  body extent -3.86,-3.29 5.84,3.29, height 2.48
E_900x700x900 [mm] "TH, 2- Leads, Body 9x7mm, Pin Spacing 7.5mm"
  round 1.4 hole 0.9: 1(-3.75,0) 2(3.75,0)
  silkscreen extent -4.5,-3.5 4.5,3.5, body extent -4.49,-3.5 4.49,3.5, height 11.96
ECWF_L_1250x620x1050 [mm] "TH, 2-Leads, Body 12.5x6.2mm, Pin Spacing 10mm"
  round 1.35 hole 0.85: 1(-5,0) 2(5,0)
  silkscreen extent -6.25,-3.1 6.25,3.1, body extent -6.25,-3.1 6.25,3.1, height 10.5
EMC2 [mm] "Welwyn"
  round 1.6 hole 1.1: 1(-7.6,0) 2(7.6,0)
  silkscreen extent -6.42,-2 6.42,2, body extent -8.02,-2 8.02,2, height 3.98
FCC_disclaimer [mil]
FM_630x1120 [mm] "PANASONIC"
  rect 1.45x1.45 hole 0.787: 1(-1.25,0)
  round 1.45 hole 0.787: 2(1.25,0)
  silkscreen extent -3.4,-3.4 3.4,3.4, body extent -3.37,-3.39 3.4,3.39, height 12.71
FP-MT6224-AHRG-A_RADIAL-MFG [mm]
  rrect5% 1.9x1.9 hole 1.25 paste-1000 mask+0: 1(-2.54,0)
  round 1.9 hole 1.25 paste-1000 mask+0: 2(0,0) 3(2.54,0)
  silkscreen extent -4.2,-3.07 2.6,3.07, body extent -3.72,-3.72 3.72,3.72, height 0.25
FP-YXBCM020013007C_PTH_CHOKE_12MM5_25MM0-MFG [mm]
  rrect5% 1.9x1.9 hole 1.25 paste-1000 mask+0: 1(4.5,5.5)
  round 1.9 hole 1.25 paste-1000 mask+0: 2(4.5,-5.5) 3(-4.5,-5.5) 4(-4.5,5.5)
  silkscreen extent -6.25,-12.5 6.87,12.5, body extent -6.35,-12.6 6.35,12.6, height 0.25
FUSE_0216 [mm] "LITTELFUSE"
  round 1.8 hole 1.041: 1(-13,0) 2(13,0)
  silkscreen extent -11.8,-2.65 11.8,2.65, body extent -13.32,-2.65 13.32,2.65, height 5.3
GBJ [mm] "Micro Commercial Components"
  rect 2.3x2.3 hole 1.6: 1(-12.5,0)
  round 2.3 hole 1.6: 2(-2.5,0) 3(5,0) 4(12.5,0)
  silkscreen extent -15.3,-1.8 15,3.1, body extent -15.25,-1.75 15.05,3.05, height 24.3
Heatsink1 [mm]
  rect 2.6x2 hole 1.2 square: 1(110,-0.6)
  silkscreen extent 0,0 120,3, body extent 0,0 120,3, height 40
Heatsink2 [mm]
  rect 2.6x2 hole 1.2 square: 1(5,-0.6)
  silkscreen extent 0,0 40,3, body extent 0,0 40,3, height 40
HXG_2500x4000 [mm] "TH, 2-Leads, Dia 25mm, Pin Spacing 10mm"
  rect 2.5x2.5 hole 2: 1(-5,0)
  round 2.5 hole 2: 2(5,0)
  silkscreen extent -13,-13 13,13, body extent -12.9,-12.97 13.1,12.97, height 42
IEC_HighVoltage_Small [mil]
  silkscreen extent -107,-88 107,97
IEC_HotSurface_Small [mil]
  silkscreen extent -107,-93 107,92
Kemet_1800x850x1450 [mm] "TH, 2-Leads, Body 18x8.5mm, Pin Spacing 15mm"
  round 1.35 hole 0.9: 1(-7.5,0) 2(7.5,0)
  silkscreen extent -9.25,-4.35 9.25,4.35, body extent -9.25,-4.35 9.25,4.35, height 14.6
ML_500x500 [mm] "Rubycon"
  rect 1.2x1.2 hole 0.711: 1(-1,0)
  round 1.2 hole 0.711: 2(1,0)
  silkscreen extent -2.75,-2.75 2.75,2.75, body extent -2.73,-2.75 2.75,2.75, height 6.51
Molex_0022284043 [mm] "Header, 2.54mm, 4x1, TH"
  rect 1.55x1.55 hole 1.02: 1(-3.81,0)
  round 1.55 hole 1.02: 2(-1.27,0) 3(1.27,0) 4(3.81,0)
  silkscreen extent -5.08,-1.24 5.08,1.5, body extent -5.08,-1.24 5.08,1.24, height 8.4
Molex_0705430001 [mm] "Header(shrouded), 2.54mm, 2x1, TH"
  rect 1.6x1.6 hole 1.09: 1(-1.27,0)
  round 1.6 hole 1.09: 2(1.27,0)
  silkscreen extent -4,-4.06 3.68,2.54, body extent -3.68,-4.06 3.68,2.54, height 11.81
Phoenix_1714968 [mm] "Phoenix"
  rect 2x2 hole 1.3: 1(-6.35,0)
  round 2 hole 1.3: 2(0,0) 3(6.35,0)
  silkscreen extent -10.33,-7.88 9.57,4.6, body extent -10.06,-7.9 9.56,4.6, height 21.5
PQ2020 [mm]
  rrect6% 1.75x1.75 hole 1.25: 1(-10.16,10.16)
  round 1.75 hole 1.25 paste+0: 6(-10.16,-10.16)
  round 1.75 hole 1.25: 7(10.16,-10.16) 14(10.16,10.16)
  silkscreen extent -12.95,-12 12.27,12, body extent -12.27,-12 12.27,12, height 23.49
PQ3230_1 [mm]
  rect 2.1x2.1 hole 1.6: 1(-15.24,13.905)
  round 2.1 hole 1.6: 2(-15.24,8.825) 5(-15.24,-8.825) 6(-15.24,-13.905) 7(15.24,-13.905) 12(15.24,13.905)
  silkscreen extent -18.67,-17.78 18.67,17.78, body extent -18.67,-17.78 18.67,17.78, height 34.29
PQ3230_2 [mm]
  rect 2.1x2.1 hole 1.6: 1(-15.24,13.905)
  round 2.1 hole 1.6: 3(-15.24,3.745) 6(-15.24,-13.905) 7(15.24,-13.905) 8(15.24,-8.825) 9(15.24,-3.745) 10(15.24,3.745) 11(15.24,8.825) 12(15.24,13.905)
  silkscreen extent -18.67,-17.78 18.67,17.78, body extent -18.67,-17.78 18.67,17.78, height 34.29
Renco_RLTI-1186 [mm] "TH, 9-Leads, Body 790x540mil"
  rect 1.4x1.4 hole 0.9: 1(-7.671,5.436)
  round 1.4 hole 0.9: 2(-7.671,2.718) 3(-7.671,0) 4(-7.671,-2.718) 5(-7.671,-5.436) 6(7.671,-5.22) 7(7.671,-1.74) 8(7.671,1.74) 9(7.671,5.22)
  silkscreen extent -10.41,-6.86 10.03,6.86, body extent -10.03,-6.86 10.03,6.86, height 10.91
SMA [mm] "Molded Diode, 2-Leads, Body 4.3x2.6mm, IPC Medium Density, based on OnSemi component dimensions and land pattern"
  rect 2x2 smd: 1(-2,0) 2(2,0)
  silkscreen extent -3.66,-1.57 2.79,1.57, body extent -2.6,-1.3 2.6,1.3, height 2.42
SOD-123 [mm] "On Semi recommended land pattern"
  rect 0.915x1.22 smd: 1(-1.637,0) 2(1.637,0)
  silkscreen extent -2.74,-1.17 2.03,1.17, body extent -1.93,-0.9 1.93,0.9, height 1.35
SOD-323 [mm] "NXP recommended land pattern"
  rect 0.6x0.6 smd paste-0.05: 1(-1.1,0) 2(1.1,0)
  silkscreen extent -2.06,-0.86 1.53,0.86, body extent -1.3,-0.67 1.3,0.68, height 1.1
SOT-23 [mm] "SOT23, 3-Leads, Body 2.9x1.3mm, Pitch 0.95mm, Lead Span 2.5mm, IPC Medium Density"
  rrect50% 1x0.6 smd: 1(-1.2,0.95) 2(-1.2,-0.95) 3(1.2,0)
  silkscreen extent -1.63,-1.5 0.7,1.5, body extent -1.16,-1.45 1.21,1.45, height 1
SOT-323 [mm] "Diodes Inc recommended land pattern.  2016-02-24"
  rrect21% 0.6x0.47 smd: 1(-0.95,0.65) 2(-0.95,-0.65) 3(0.95,0)
  silkscreen extent -1.14,-1.22 0.77,1.22, body extent -1.13,-1.13 1.12,1.12, height 1.13
TO-92AP [mm] "TO, Flat Index; 3 In-Line, Axial Leads; Body Dia. 5mm; Leads 0.55 x 0.50 mm (max)"
  rect 1.5x1.5 hole 0.75: 1(-2.54,0)
  round 1.5 hole 0.75: 2(0,0) 3(2.54,0)
  silkscreen extent -2.42,-1.53 2.44,2.66, body extent -2.87,-1.53 2.87,2.66, height 9.33
TO-220-F2 [mm] "CREE"
  rect 1.9x1.9 hole 1.4: 1(-2.54,0)
  round 1.9 hole 1.4: 2(2.54,0)
  silkscreen extent -5.25,-1.64 5.26,3.01, body extent -5.25,-1.64 5.26,3.01, height 19.09
TO-220AB [mil] "Copied from Altium's version of TO3B"
  rrect25% 76x118.11 hole 50: 1(-100,0)
  oval 76x118.11 hole 50: 2(0,0) 3(100,0)
  silkscreen extent -221,-59 221,126, body extent -221,-59 221,126, height 765
TO-220FP [mm] "FM, Body 10.4x4.6mm, Pitch 2.55mm"
  rrect50% 1.95x1.95 hole 1.3: 1(-2.55,0)
  round 1.95 hole 1.3: 2(0,-2.526) 3(2.55,0)
  silkscreen extent -5.1,-1.5 5.08,3, body extent -5.09,-1.5 5.09,3, height 19.41
TO-247 [mil] "Standard TO-247"
  rrect50% 95x95 / inner round 78 / far side rrect50% 95x95 hole 62: 1(-215,0)
  round 95 / inner round 78 / far side round 95 hole 62: 2(0,0) 3(215,0)
  silkscreen extent -318,-124 318,81, body extent -318,-124 318,81, height 1007
UES_1600x2500 [mm] "TH, 2-Leads, Dia 16mm, Lead Spacing 7.5mm"
  rrect50% 1.575x1.575 hole 1.05: 1(-3.75,0)
  round 1.575 hole 1.05: 2(3.75,0)
  silkscreen extent -8.3,-8.3 8.3,8.3, body extent -8,-8 8.01,8, height 26.51
VAR_S10K275E2 [mm] "EPCOS"
  round 1.6 hole 1.1: 1(-3.75,1.1) 2(3.75,-1.1)
  silkscreen extent -6,-2.7 6,2.7, body extent -5.98,-2.7 5.98,2.7, height 14.99
WCAP-FTX2_1500x700x1250 [mm] "TH, 2-Leads, Body 15x7mm, Pin Spacing 12.5mm"
  round 1.4 hole 0.9: 1(-6.25,0) 2(6.25,0)
  silkscreen extent -7.5,-3.6 7.5,3.6, body extent -7.5,-3.5 7.5,3.5, height 12.3
WE-CMB_NiZn_S [mm] "TH, 4-Leads, Body 18.5x14.5mm"
  rect 1.8x1.8 hole 1.3: 1(-2.5,3.85)
  round 1.8 hole 1.3: 2(2.5,3.85) 3(2.5,-3.85) 4(-2.5,-3.85)
  silkscreen extent -6.5,-8.1 6.5,8.37, body extent -6.53,-8.09 6.52,8.09, height 19.55
WE-CMBNC_L [mm] "TH, 4-Leads, Body 19x28mm"
  rrect6% 1.7x1.7 hole 1.2: 1(-6,5)
  round 1.7 hole 1.2: 2(-6,-5) 3(6,-5) 4(6,5)
  silkscreen extent -9,-13.75 9,13.75, body extent -9,-13.75 9,13.75, height 25.47
WEEE_Minimum [mil] "WEEElie bin"
  silkscreen extent -95,-172 99,104
Wurth_691216510002 [mm] "Receptacle, 5.08mm, 2x1, TH"
  rect 2.1x2.1 hole 1.6: 1(-2.54,0)
  round 2.1 hole 1.6: 2(2.54,0)
  silkscreen extent -5.4,-4.9 5.68,5.2, body extent -5.1,-4.9 5.66,5.2, height 13.8

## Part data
C1 C2: library part CMP-0078590-1, "CAP, Film, 0.47 µF, X2 275 VAC, +/- 10%, TH", Cap_Case=18x8.5x14.5, Manufacturer=Kemet, Supplier Part Number 1=80-R46KI347050P0K, Tolerance_%=10%, ValueDisplayed=0.47µF
C3 C15 C17: library part CMP-0008346-2, "CAP, CERM, 4.7 uF, 25 V, +/- 10%, X7R, 0805", Cap_Case=0805, Manufacturer=MuRata, Supplier Part Number 1=490-9962-1-ND, TempCo=X7R, Tolerance_%=10%, Value1=Unknown, Value2=25V, ValueDisplayed=4.7uF
C4: library part CMP-0007198-4, "CAP, CERM, 2200 pF, 50 V, +/- 5%, C0G/NP0, 0603", Cap_Case=0603, Manufacturer=MuRata, Supplier Part Number 1=490-1459-1-ND, TempCo=C0G/NP0, Tolerance_%=5%, Value1=Unknown, Value2=50V, ValueDisplayed=2200pF
C5: library part CMP-0012412-3, "CAP, Film, 1.2 uF, 450 V, +/- 10%, TH", Manufacturer="Panasonic Electronic Components", Supplier Part Number 1=495-6910-ND, Tolerance_%=10%, Value1=Unknown, Value2=450V, ValueDisplayed=1.2uF
C6: library part CMP-0007172-4, "CAP, CERM, 1000 pF, 50 V, +/- 1%, C0G/NP0, 0603", Cap_Case=0603, Manufacturer=MuRata, Supplier Part Number 1=490-6377-1-ND, TempCo=C0G/NP0, Tolerance_%=1%, Value1=Unknown, Value2=50V, ValueDisplayed=1000pF
C7: library part CMP-0007573-2, "CAP, CERM, 2.2 uF, 25 V, +/- 10%, X7R, 0805", Cap_Case=0805, Manufacturer=AVX, Supplier Part Number 1=478-5719-1-ND, TempCo=X7R, Tolerance_%=10%, Value1=Unknown, Value2=25V, ValueDisplayed=2.2uF
C8: library part CMP-0006867-4, "CAP, CERM, 1 uF, 25 V, +/- 10%, X7R, 0603", Cap_Case=0603, Manufacturer=Kemet, Supplier Part Number 1=399-7376-1-ND, TempCo=X7R, Tolerance_%=10%, Value1=Unknown, Value2=25V, ValueDisplayed=1uF
C9: library part CMP-0007203-4, "CAP, CERM, 270 pF, 50 V, +/- 5%, C0G/NP0, 0603", Cap_Case=0603, Manufacturer=MuRata, Supplier Part Number 1=490-1437-1-ND, TempCo=C0G/NP0, Tolerance_%=5%, Value1=Unknown, Value2=50V, ValueDisplayed=270pF
C10 C13: library part CMP-0007877-2, "CAP, CERM, 2.2 uF, 50 V, +/- 10%, X7R, 0805", Cap_Case=0805, Manufacturer=TDK, Supplier Part Number 1=445-5968-1-ND, TempCo=X7R, Tolerance_%=10%, Value1="0.00366 ohm", Value2=50V, ValueDisplayed=2.2uF
C11: library part CMP-0009979-2, "CAP, AL, 220 uF, 450 V, +/- 20%, TH", Cap_Case=25x40mm, Manufacturer=Rubycon, Supplier Part Number 1=1189-1974-ND, Tolerance_%=20%, Value1=Unknown, Value2=450V, ValueDisplayed=220uF
C12: library part CMP-0007424-4, "CAP, CERM, 0.47 uF, 25 V, +/- 10%, X7R, 0603", Cap_Case=0603, Manufacturer=MuRata, Supplier Part Number 1=490-3291-1-ND, TempCo=X7R, Tolerance_%=10%, Value1=Unknown, Value2=25V, ValueDisplayed=0.47uF
C14: library part CMP-0012506-3, "CAP, Film, 0.022 uF, 630 V, +/- 3%, TH", Cap_Case=12.5x6.2x10.5mm, Manufacturer=Panasonic, Supplier Part Number 1=P12125-ND, Tolerance_%=3%, Value1=Unknown, Value2=630V, ValueDisplayed=0.022uF
C16 C29 C32 C35 C36 C43 C45 C47 C57: library part CMP-0007404-4, "CAP, CERM, 0.1 uF, 25 V, +/- 10%, X7R, 0603", Cap_Case=0603, Manufacturer=MuRata, Supplier Part Number 1=490-1524-1-ND, TempCo=X7R, Tolerance_%=10%, Value1=Unknown, Value2=25V, ValueDisplayed=0.1uF
C18: library part CMP-0006788-4, "CAP, CERM, 3.9 pF, 50 V, +/- 6%, C0G/NP0, 0603", Cap_Case=0603, Manufacturer=AVX, Supplier Part Number 1=478-1158-1-ND, TempCo=C0G/NP0, Tolerance_%=6%, Value1="0.712 ohm", Value2=50V, ValueDisplayed=3.9pF
C19: library part CMP-0006944-4, "CAP, CERM, 0.47 uF, 16 V, +/- 10%, X7R, 0603", Cap_Case=0603, Manufacturer=Kemet, Supplier Part Number 1=399-4922-1-ND, TempCo=X7R, Tolerance_%=10%, Value1=Unknown, Value2=16V, ValueDisplayed=0.47uF
C20 C28: library part CMP-0007171-4, "CAP, CERM, 100 pF, 50 V, +/- 5%, C0G/NP0, 0603", Cap_Case=0603, Manufacturer=MuRata, Supplier Part Number 1=490-1427-1-ND, TempCo=C0G/NP0, Tolerance_%=5%, Value1=Unknown, Value2=50V, ValueDisplayed=100pF
C21: library part CMP-0008342-2, "CAP, CERM, 2.2 uF, 25 V, +/- 10%, X7R, 0805", Cap_Case=0805, Manufacturer=MuRata, Supplier Part Number 1=490-3331-1-ND, TempCo=X7R, Tolerance_%=10%, Value1="0.005 ohm", Value2=25V, ValueDisplayed=2.2uF
C22 C23: library part CMP-0012312-3, "CAP, Film, 0.022 uF, 800 V, +/- 3%, TH", Cap_Case=15x7x12.5, Manufacturer="Panasonic Electronic Components", Supplier Part Number 1=P14259-ND, Tolerance_%=10%, Value1=Unknown, Value2=800V, ValueDisplayed=0.022uF
C24 C26: library part CMP-0009034-2, "CAP, CERM, 47 pF, 1000 V, +/- 5%, C0G/NP0, 1206", Cap_Case=1206, Manufacturer=Vishay-Vitramon, Supplier Part Number 1=720-1015-1-ND, TempCo=C0G/NP0, Tolerance_%=5%, Value1=Unknown, Value2=1000V, ValueDisplayed=47pF
C25: library part CMP-0007465-4, "CAP, CERM, 8200 pF, 50 V, +/- 10%, X7R, 0603", Cap_Case=0603, Manufacturer=MuRata, Supplier Part Number 1=490-1510-1-ND, TempCo=X7R, Tolerance_%=10%, Value1=Unknown, Value2=50V, ValueDisplayed=8200pF
C27: library part CMP-0007415-4, "CAP, CERM, 0.22 uF, 25 V, +/- 10%, X7R, 0603", Cap_Case=0603, Manufacturer=MuRata, Supplier Part Number 1=490-3290-1-ND, TempCo=X7R, Tolerance_%=10%, Value1=Unknown, Value2=25V, ValueDisplayed=0.22uF
C30: library part CMP-0078358-1, "CAP, CERM, 2200 pF, X1 400 VAC/Y1 400 VAC, +/- 20%, Y5V, D9xL13mm", Cap_Case=9x13mm, Manufacturer=Kemet, Supplier Part Number 1=399-9487-1-ND, TempCo=Y5V, Tolerance_%=20%, ValueDisplayed=2200pF
C31: library part CMP-0006978-4, "CAP, CERM, 0.01 uF, 50 V, +/- 10%, X7R, 0603", Cap_Case=0603, Manufacturer=Kemet, Supplier Part Number 1=399-5346-1-ND, TempCo=X7R, Tolerance_%=10%, Value1=Unknown, Value2=50V, ValueDisplayed=0.01uF
C33: library part CMP-0007402-4, "CAP, CERM, 1000 pF, 25 V, +/- 10%, X7R, 0603", Cap_Case=0603, Manufacturer=MuRata, Supplier Part Number 1=GRM188R71E102KA01D-ND, TempCo=X7R, Tolerance_%=10%, Value1=Unknown, Value2=25V, ValueDisplayed=1000pF
C34: library part CMP-0006986-4, "CAP, CERM, 470 pF, 50 V, +/- 10%, X7R, 0603", Cap_Case=0603, Manufacturer=Kemet, Supplier Part Number 1=399-5338-1-ND, TempCo=X7R, Tolerance_%=10%, Value1=Unknown, Value2=50V, ValueDisplayed=470pF
C37 C38: library part CMP-0074690-1, "CAP, CERM, 100 pF, 250 V,+/- 5%, C0G/NP0, 0805", Cap_Case=0805, Manufacturer="Samsung Electro-Mechanics", Supplier Part Number 1=1276-6631-1-ND, TempCo=C0G/NP0, Tolerance_%=5%, Value2=250V, ValueDisplayed=100pF
C39 C41: library part CMP-0077674-1, "CAP, AL, 680 µF, 80 V, +/- 20%, TH", Cap_Case=16x25mm, Manufacturer="Panasonic Electronic Components", Supplier Part Number 1=PCE5219-ND, Tolerance_%=20%, Value2=80V, ValueDisplayed=680µF
C40: library part CMP-0007042-4, "CAP, CERM, 0.22 uF, 25 V, +/- 10%, X7R, 0603", Cap_Case=0603, Manufacturer=TDK, Supplier Part Number 1=445-5191-1-ND, TempCo=X7R, Tolerance_%=10%, Value1=Unknown, Value2=25V, ValueDisplayed=0.22uF
C42: library part CMP-0006977-4, "CAP, CERM, 0.01 uF, 100 V, +/- 10%, X7R, 0603", Cap_Case=0603, Manufacturer=Kemet, Supplier Part Number 1=399-5347-1-ND, TempCo=X7R, Tolerance_%=10%, Value1=Unknown, Value2=100V, ValueDisplayed=0.01uF
C44 C46: library part CMP-0008970-2, "CAP, CERM, 1 uF, 100 V, +/- 10%, X7R, 1206", Cap_Case=2220, Manufacturer=MuRata, Supplier Part Number 1=490-3909-1-ND, TempCo=X7R, Tolerance_%=10%, Value1=Unknown, Value2=100V, ValueDisplayed=1uF
C48: library part CMP-0010292-1, "CAP, AL, 22 uF, 25 V, +/- 20%, TH", Cap_Case=5x5, Manufacturer=Rubycon, Supplier Part Number 1=25ML22MEFC5X5-ND, Tolerance_%=20%, Value1=Unknown, Value2=25V, ValueDisplayed=22uF
C49: library part CMP-0010339-1, "CAP, AL, 100 uF, 25 V, +/- 20%, 0.13 ohm, TH", Cap_Case=6.3x11.2, Manufacturer=Panasonic, Supplier Part Number 1=P12924-ND, Tolerance_%=20%, Value1="0.13 ohm", Value2=25V, ValueDisplayed=100uF
C50: library part CMP-0860549-1, "CAP, CERM, 1 µF, 25 V,+/- 10%, X7R, 0603", Cap_Case=0603, Manufacturer=TDK, TempCo=X7R, Tolerance_%=10%, Value2=25V, ValueDisplayed=1µF
C51 C53: library part CMP-0007534-2, "CAP, CERM, 470 pF, 100 V, +/- 5%, C0G/NP0, 0805", Cap_Case=0805, Manufacturer=AVX, Supplier Part Number 1=478-1288-1-ND, TempCo=C0G/NP0, Tolerance_%=5%, Value1="0.159 ohm", Value2=100V, ValueDisplayed=470pF
C52 C58: library part CMP-0008912-2, "CAP, CERM, 2200 pF, 630 V, +/- 10%, X7R, 1206", Cap_Case=1206, Manufacturer=MuRata, Supplier Part Number 1=490-3508-1-ND, TempCo=X7R, Tolerance_%=10%, Value1=Unknown, Value2=630V, ValueDisplayed=2200pF
C54: library part CMP-0010404-1, "CAP, AL, 220 uF, 25 V, +/- 20%, TH", Cap_Case=8x11.5, Manufacturer=Chemi-Con, Supplier Part Number 1=565-1674-ND, Tolerance_%=20%, Value1=Unknown, Value2=25V, ValueDisplayed=220uF
C55 C56: library part CMP-0008136-2, "CAP, CERM, 1 uF, 25 V, +/- 10%, X5R, 0805", Cap_Case=0805, Manufacturer=MuRata, Supplier Part Number 1=490-1700-1-ND, TempCo=X5R, Tolerance_%=10%, Value1="0.009 ohm", Value2=25V, ValueDisplayed=1uF
CY1 CY2: "CAP, CERM, 2200 pF, 300 V, +/- 20%, E, TH, 2- Leads, Body 9x7mm, Pin Spacing 7.5mm", Cap_Case=9x7x9mm, Manufacturer=MuRata, Supplier Part Number 1=DE6E3KJ222MN3A-ND, TempCo=E, Tolerance_%=20, Value1=Unknown, Value2=300V, ValueDisplayed=2200pF
D1: library part CMP-0082068-2, "Diode, P-N-Bridge, 600 V, 25 A, TH", Manufacturer="Micro Commercial Components", Value1=25A, Value2=1.05V
D2: library part CMP-0029178-2, "Diode, Switching, 250 V, 0.4 A, SOT-23", Manufacturer="ON Semiconductor", Value1=0.4A, Value2=1.25V
D3: library part CMP-0029223-3, "Diode, Switching-Bridge, 600 V, 3 A, TH", Manufacturer=Vishay-Semiconductor, Value1=3A, Value2=1.2V
D4 D7 D8: library part CMP-0029001-2, "Diode, Ultrafast, 100 V, 0.15 A, SOD-123", Manufacturer="Diodes Inc.", Value1=0.15A, Value2=1.25V
D5: library part CMP-0028618-2, "Diode, Schottky, 600 V, 4 A, TH", Manufacturer=Cree, Value1=4A, Value2=1.8V
D6: library part CMP-0085739-1, "Diode, Zener, 5.1 V, 300 mW, SOD-323", Manufacturer="ON Semiconductor", Power_W=300mW, Value1=0.3W
D9: library part CMP-0067545-2, "Diode, Superfast Rectifier, 600 V, 1 A, SMA", Manufacturer="SMC Diode Solutions", Value1=1A, Value2=1.7V
D10: library part CMP-0028627-2, "Diode, Schottky, 30 V, 0.2 A, SOT-323", Manufacturer="Micro Commercial Components", Value1=0.2A, Value2=1V
D11 D12: library part CMP-0028764-3, "Diode, Schottky, 200 V, 20 A, TH", Manufacturer="Taiwan Semiconductor Corporation", Value1=20A, Value2=0.99V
